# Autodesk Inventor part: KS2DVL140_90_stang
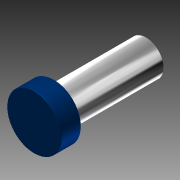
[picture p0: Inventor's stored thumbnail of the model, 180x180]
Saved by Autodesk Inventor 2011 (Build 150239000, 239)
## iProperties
Created: 2010-11
Document SubType Name: Modeling
Designer: TB
Mass: 161.233 g
Surface Area: 236.814 cm^2
Volume: 161.233 cm^3
Density: 1 g/cm^3
Author: TB
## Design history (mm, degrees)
sketch "Sketch2"
  geometry: L1 (-35, -3)-(-35, 3) reference; L2 (-35, -9)-(-35, 9) reference; L3 (-35, 45)-(-324, 45); L4 (-324, 45)-(-324, 0); L5 (-324, 0)-(-35, 0); L6 (-35, 0)-(-35, 45); L7 (-324, 45)-(-272, 45); L8 (-272, 45)-(-272, 70); L9 (-272, 70)-(-324, 70); L10 (-324, 70)-(-324, 45); 1 further point
  constraints: 16 end point, 4 parallel, 2 horizontal, 2 perpendicular, 1 midpoint
  dimensions: "Dia" = 90 diameter of L3 L5; "d3" = 289 distance of L3.start L3.end (computed from Slaglengde, Forlengelse_rør); "StempelDia" = 140 diameter of L9 L5; "StempelLengde" = 52 distance of L8.end L9.end
revolve "Revolution1" sketch "Sketch2" stored, may be unused: angle "d6" = 90 deg
fillet "Fillet1" dims "d7" = 2
sketch "Sketch3"
  geometry: L1 (-324, -68)-(-324, 68) reference; L2 (-324, 0)-(-324.01, 0); L3 (-324, 0)-(-324, 0.01); A1 r 0.01 centre (-324, 0) between (-324, 0.01) and (-324.01, 0); 1 further point
  constraints: 4 end point, 2 point on circle, 1 centre point, 1 midpoint, 1 perpendicular, 1 point on line
  dimensions: "d8" = 0.01 distance of L2.start L2.end; "d9" = 0.01 distance of L2.start L3.end (= d8); "d10" = 0.01 radius of A1 (= d8)
revolve "Revolution2" sketch "Sketch3" stored, may be unused: angle "d11" = 90 deg
body "Solid1"
node "Projected Loop2"
other parameters: "Forlengelse_rør" = 0
